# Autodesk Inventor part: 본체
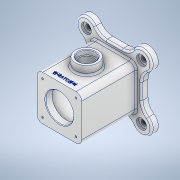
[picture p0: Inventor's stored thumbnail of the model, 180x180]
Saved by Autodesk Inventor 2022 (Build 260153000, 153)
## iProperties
Created: 2022-05
Part Number: 본체
Material: 알루미늄 6061
Document SubType Name: Modeling
Designer: admin
Mass: 1073.63 g
Surface Area: 878.617 cm^2
Volume: 397.642 cm^3
Density: 2.7 g/cm^3
Appearance: 알루미늄 - 평지
Author: admin
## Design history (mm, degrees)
sketch "스케치1" dims "d2" = 140
  geometry: L1 (-49, -49)-(49, -49); L2 (49, -49)-(49, 49); L3 (49, 49)-(-49, 49); L4 (-49, 49)-(-49, -49); L5 (-49, -49)-(49, 49); L6 (49, -49)-(-49, 49); L7 (49, 49)-(50.23, 50.23); L8 (0, -98.983)-(0, 103.897) reference; L9 (-100.773, 0)-(114.637, 0) reference; L10 (49.458, 74.914)-(24.842, 50.298); L11 (83.864, 58.408)-(54.491, 29.035); C1 r 18 at (49.497, 49.497); C2 r 18 at (49.497, 49.497); C3 r 18 at (-49.497, 49.497); C4 r 18 at (49.497, -49.497); C5 r 18 at (-49.497, -49.497); 10 further points
  constraints: 18 end point, 5 centre point, 3 symmetric about line, 2 coincident, 2 midpoint, 2 parallel, 2 tangent, 1 horizontal, 1 perpendicular, 1 point on line, 6 other
  dimensions: "d0" = 98 distance of L3.end L2.end; "d1" = 98 distance of L2.end L1.end; "d5" = 45 deg angle of L7 L3; "d6" = 36 diameter of C1; "d73" = 135 deg angle of L10 L3; "d74" = 45 deg angle of L3 L11
extrude "돌출1" new body sketch "스케치1" distance "d7" = 12; taper "d8" = 0 deg
fillet "모깎기1" dims "d9" = 25
sketch "스케치2"
  geometry: L1 (-40, -40)-(40, -40); L2 (40, -40)-(40, 40); L3 (40, 40)-(-40, 40); L4 (-40, 40)-(-40, -40); L5 (-40, -40)-(40, 40); L6 (40, -40)-(-40, 40); 1 further point
  constraints: 12 end point, 2 midpoint, 2 parallel, 1 horizontal, 1 perpendicular
  dimensions: "d10" = 80 distance of L3.end L2.end; "d11" = 80 distance of L1.end L2.end
extrude "돌출2" join sketch "스케치2" distance "d12" = 98; taper "d13" = 0 deg
sketch "스케치3"
  geometry: L1 (0, -22)-(0, 132) reference; L2 (40, 110)-(-40, 110) reference; L3 (0, 110)-(25, 110); L4 (25, 110)-(25, 98); L5 (25, 98)-(0, 98); L6 (0, 98)-(0, 110); L7 (0, 98)-(35, 98); L8 (35, 98)-(35, 12); L9 (35, 12)-(0, 12); L10 (0, 12)-(0, 98); L11 (0, 12)-(25, 12); L12 (25, 12)-(25, 0); L13 (25, 0)-(0, 0); L14 (0, 0)-(0, 12); 4 further points
  constraints: 24 end point, 6 parallel, 3 horizontal, 3 perpendicular, 1 midpoint
  dimensions: "d14" = 50 diameter of L12 L1; "d15" = 50 diameter of L4 L1; "d16" = 70 diameter of L8 L1; "d17" = 12 distance between parallel lines of L5 L2; "d18" = 86 distance between parallel lines of L11 L5; "d19" = 12 distance between parallel lines of L11 L13
revolve "회전1" sketch "스케치3" stored, may be unused: angle "d20" = 90 deg
node "작업 평면1"
sketch "스케치4"
  geometry: L1 (34.706, 12)-(14.162, 12) reference; L2 (0, -16.2)-(0, 97.2) reference; C1 r 20 at (0, 61); 1 further point
  constraints: 1 centre point, 1 point on line
  dimensions: "d22" = 40 diameter of C1; "d23" = 49 distance from line of C1.centre L1
extrude "돌출3" join sketch "스케치4" stored distance "d24" = 98; taper "d25" = 0 deg
sketch "스케치5"
  geometry: C1 r 20 at (0, 0) reference; C2 r 15 at (0, 0); 1 further point
  constraints: 1 centre point, 1 coincident
  dimensions: "d26" = 30 diameter of C2
extrude "돌출4" cut sketch "스케치5" distance "d27" = 8; taper "d28" = 0 deg
sketch "스케치6"
  geometry: C1 r 20 at (0, 0) reference; C2 r 12.5 at (0, 0); 1 further point
  constraints: 1 centre point, 1 coincident
  dimensions: "d29" = 25 diameter of C2
extrude "돌출5" cut sketch "스케치6" stored distance "d30" = 8; taper "d31" = 0 deg
sketch "스케치7"
  geometry: L1 (-30, -30)-(30, -30); L2 (30, -30)-(30, 30); L3 (30, 30)-(-30, 30); L4 (-30, 30)-(-30, -30); L5 (-30, -30)-(30, 30); L6 (30, -30)-(-30, 30); 5 further points
  constraints: 12 end point, 3 coincident, 2 midpoint, 2 parallel, 1 horizontal, 1 perpendicular, 1 point on line
  dimensions: "d32" = 60 distance of L3.end L2.end; "d33" = 60 distance of L1.end L2.end
hole "구멍1" sketch "스케치7" at (-30, 30), (30, 30), (-30, -30), (30, -30) diameter "d34" = 3.242; stored, may be unused: countersink angle "d38" = 90 deg, drill point angle "d40" = 118 deg; dims "d35" = 8, "d36" = 4, "d37" = 2, "d39" = 10
sketch "스케치8"
  geometry: L1 (-30, -30)-(30, -30); L2 (30, -30)-(30, 30); L3 (30, 30)-(-30, 30); L4 (-30, 30)-(-30, -30); L5 (-30, -30)-(30, 30); L6 (30, -30)-(-30, 30); C1 r 1.621 at (-30, 30) reference; C2 r 1.621 at (30, 30) reference; C3 r 1.621 at (30, -30) reference; C4 r 1.621 at (-30, -30) reference; 5 further points
  constraints: 12 end point, 4 coincident, 2 midpoint, 2 parallel, 1 horizontal, 1 perpendicular
  dimensions: "d41" = 60 distance of L3.end L2.end; "d42" = 60 distance of L2.end L1.end
hole "구멍2" sketch "스케치8" at (-30, 30), (30, 30), (30, -30), (-30, -30) diameter "d43" = 3.242; stored, may be unused: countersink angle "d47" = 90 deg, drill point angle "d49" = 118 deg; dims "d44" = 8, "d45" = 4, "d46" = 2, "d48" = 10
sketch "스케치9"
  geometry: A1 r 18 centre (-49.497, 49.497) between (-34.706, 59.754) and (-59.754, 34.706) reference; 2 further points
  constraints: 1 coincident
hole "구멍3" sketch "스케치9" at (-49.497, 49.497) diameter "d50" = 10; stored, may be unused: countersink angle "d54" = 90 deg, drill point angle "d56" = 118 deg; dims "d51" = 8, "d52" = 18, "d53" = 4, "d55" = 10
fillet "모깎기2" dims "d57" = 10
fillet "모깎기3" dims "d58" = 3
chamfer "모따기1" distance "d59" = 1; stored, may be unused: second distance "d60" = 2, angle "d61" = 45 deg
chamfer "모따기2" distance "d62" = 1; stored, may be unused: second distance "d63" = 2, angle "d64" = 45 deg
fillet "모깎기4" dims "d65" = 3
sketch "스케치10"
  geometry: L1 (30, 34)-(30, -120) reference; L2 (60, -98)-(0, -98) reference; 2 further points
  constraints: 1 point on line, 1 other
  dimensions: "d66" = 10 distance from line of point (30, -88) L2
feature "엠보싱1" sketch "스케치10" dims "d0" = 98, "d1" = 98, "d2" = 140, "d5" = 45 deg, "d6" = 36, "d67" = 0.5, "d68" = 0, "d73" = 135 deg, "d74" = 45 deg
chamfer "모따기3" distance "d69" = 1; stored, may be unused: second distance "d70" = 2, angle "d71" = 45 deg
fillet "모깎기5" dims "d72" = 3
node "솔리드1"
mirror "미러1"
mirror "미러2"
feature "A9D066F2-1C7D-4E18-AEED-F7BC21143FA4" dims "d50" = 10, "d51" = 8, "d52" = 18, "d53" = 4, "d54" = 90 deg, "d55" = 10, "d56" = 118 deg
other parameters: "d21" = 55
